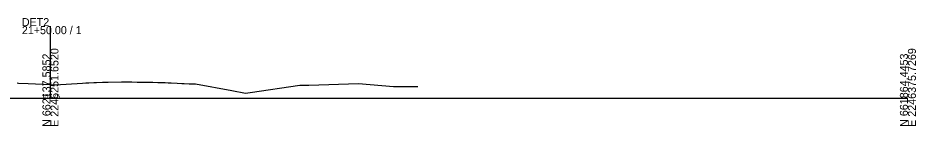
# Model space of a CAD drawing. Extents: x -26 to 603, y -10 to 9526.
# Drawn here: x 288.6 to 602.8, y 4490.3 to 4528 of the extents above; entities that cross this region are included whole.
import ezdxf

# ---------------------------------------------------------------- set-up
doc = ezdxf.new("R2010")
doc.units = 0
for name, color, linetype in [('Exist Cross Section Cell', 7, 'Continuous'), ('Exist XS Center Line Elevation Label', 7, 'Continuous'), ('Exist XS Ground Line', 7, 'Continuous')]:
    doc.layers.add(name, color=color, linetype=linetype)

msp = doc.modelspace()

# ---------------------------------------------------------------- linework, layer by layer
at = {"layer": 'Exist Cross Section Cell'}
for p, q in [((300, 4500), (300, 4525.18)), ((0, 4500), (300, 4500)), ((300, 4500), (600, 4500))]:
    msp.add_line(p, q, dxfattribs=at)
at = {"layer": 'Exist XS Ground Line'}
for p, q in [((320.18, 4505.6), (324.81, 4505.68)), ((324.81, 4505.68), (326.29, 4505.7)), ((326.29, 4505.7), (327.07, 4505.73)), ((327.07, 4505.73), (328.43, 4505.7)), ((328.43, 4505.7), (330.3, 4505.67)), ((288.4, 4505.33), (288.87, 4505.3)), ((288.87, 4505.3), (292.22, 4505.15)), ((292.22, 4505.15), (300, 4504.75)), ((300, 4504.75), (301.66, 4504.67)), ((301.66, 4504.67), (311.22, 4505.31)), ((311.22, 4505.31), (312.36, 4505.38)), ((312.36, 4505.38), (312.8, 4505.41)), ((312.8, 4505.41), (313.4, 4505.42)), ((313.4, 4505.42), (315.2, 4505.51)), ((315.2, 4505.51), (315.64, 4505.55)), ((315.64, 4505.55), (316.1, 4505.54)), ((316.1, 4505.54), (318.18, 4505.58)), ((318.18, 4505.58), (319.31, 4505.58)), ((319.31, 4505.58), (320.18, 4505.6)), ((330.3, 4505.67), (330.92, 4505.66)), ((330.92, 4505.66), (332.27, 4505.63)), ((332.27, 4505.63), (334.69, 4505.58)), ((334.69, 4505.58), (335.79, 4505.56)), ((335.79, 4505.56), (337.52, 4505.53)), ((337.52, 4505.53), (339.1, 4505.53)), ((339.1, 4505.53), (339.61, 4505.47)), ((339.61, 4505.47), (340.09, 4505.45)), ((340.09, 4505.45), (341.18, 4505.44)), ((341.18, 4505.44), (341.47, 4505.39)), ((341.47, 4505.39), (341.85, 4505.37)), ((341.85, 4505.37), (342.24, 4505.35)), ((342.24, 4505.35), (344.36, 4505.24)), ((344.36, 4505.24), (346.02, 4505.15)), ((346.02, 4505.15), (346.77, 4505.11)), ((346.77, 4505.11), (348.56, 4505.01)), ((348.56, 4505.01), (348.88, 4504.98)), ((348.88, 4504.98), (349.21, 4504.98)), ((349.21, 4504.98), (350.05, 4505)), ((350.05, 4505), (350.8, 4505.03)), ((350.8, 4505.03), (363.52, 4502.71)), ((363.52, 4502.71), (368.21, 4501.83)), ((369.9, 4502.05), (387.29, 4504.52)), ((387.29, 4504.52), (390.36, 4504.61)), ((390.36, 4504.61), (407.79, 4505.16)), ((407.79, 4505.16), (420.06, 4504.13)), ((420.06, 4504.13), (428.57, 4504.07)), ((368.21, 4501.83), (369.9, 4502.05))]:
    msp.add_line(p, q, dxfattribs=at)

# ---------------------------------------------------------------- texts
at = {"layer": 'Exist Cross Section Cell'}
for s, p in [('DET2', (290, 4525.18)), ('21+50.00 / 1', (290, 4522.38))]:
    msp.add_text(s, height=2.8, dxfattribs=at).set_placement(p)
for s, p in [('N 662137.5852', (300, 4490)), ('E 2246251.6520', (302.8, 4490)), ('N 661864.4453', (600, 4490)), ('E 2246375.7269', (602.8, 4490))]:
    msp.add_text(s, height=2.8, rotation=90, dxfattribs=at).set_placement(p)
at = {"layer": 'Exist XS Center Line Elevation Label'}
msp.add_text('152.75', height=1.5, dxfattribs=at).set_placement((296.99, 4500))

doc.saveas('drawing.dxf')
